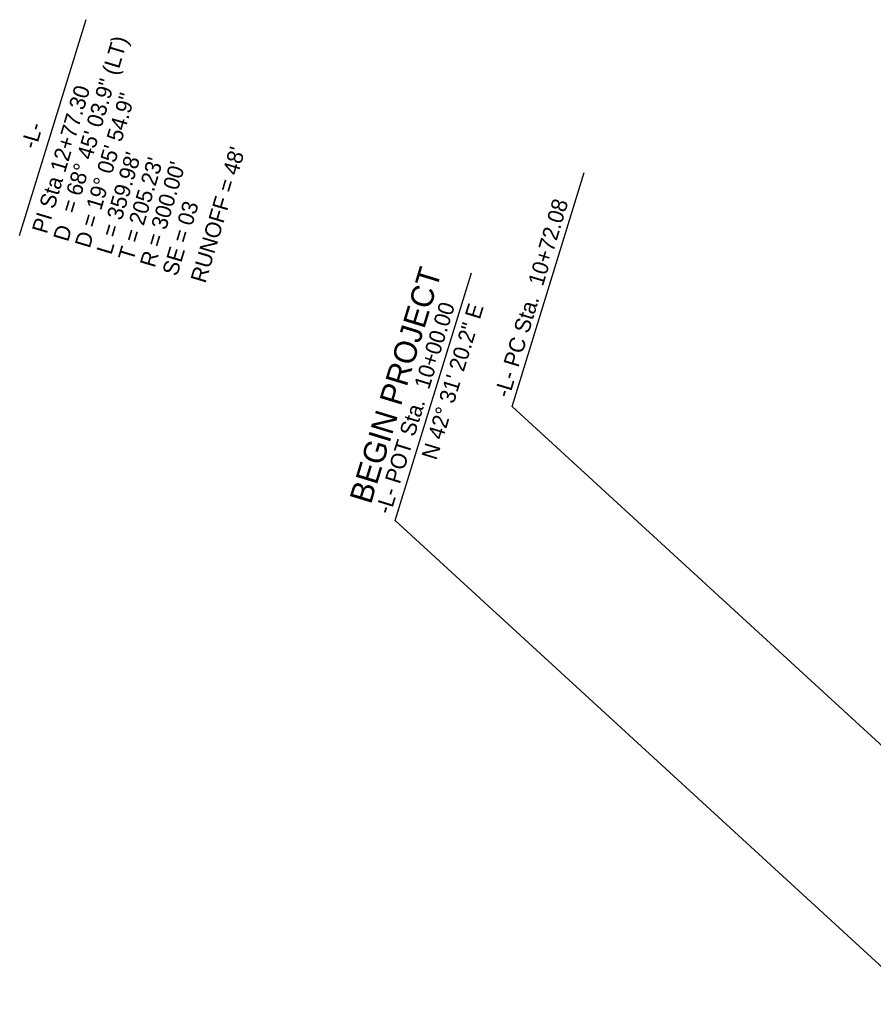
# Model space of a CAD drawing. Extents: x 1348352 to 1349119, y 1028998 to 1029749.
# Drawn here: x 1348351.6 to 1348729, y 1029075.3 to 1029508.1 of the extents above; entities that cross this region are included whole.
import ezdxf

# ---------------------------------------------------------------- set-up
doc = ezdxf.new("R2010")
doc.units = 0
for name, color, linetype in [('Prop DSN Text', 7, 'Continuous'), ('Prop Horizontal Alignment Curve and Spiral Data', 7, 'Continuous'), ('Prop Horizontal Alignment Direction Label', 7, 'Continuous'), ('Prop Horizontal Alignment Station Label', 7, 'Continuous')]:
    doc.layers.add(name, color=color, linetype=linetype)

msp = doc.modelspace()

# ---------------------------------------------------------------- linework, layer by layer
at = {"layer": 'Prop Horizontal Alignment Station Label'}
for p, q in [((1348351.59, 1029412.81), (1348380.95, 1029508.13)), ((1348569.31, 1029337.19), (1348601.13, 1029440.53)), ((1348517.58, 1029286.83), (1348551.28, 1029396.27)), ((1348796.98, 1029128.41), (1348569.31, 1029337.19)), ((1348748.26, 1029075.29), (1348517.58, 1029286.83))]:
    msp.add_line(p, q, dxfattribs=at)

# ---------------------------------------------------------------- texts
at = {"layer": 'Prop DSN Text'}
msp.add_text('BEGIN PROJECT', height=10, rotation=73.074, dxfattribs=at).set_placement((1348506.86, 1029293.68))
at = {"layer": 'Prop Horizontal Alignment Curve and Spiral Data'}
for s, p in [('= 68%%d 45\' 03.9" (LT)', (1348376.39, 1029422.05)), ('PI Sta 12+77.30', (1348363.6, 1029413.16)), ('D = 19%%d 05\' 54.9"', (1348382.57, 1029406.79)), ("RUNOFF = 48'", (1348433.72, 1029391.32)), ("L = 359.98'", (1348392.15, 1029403.92)), ("T = 205.23'", (1348401.73, 1029401.06)), ("R = 300.00'", (1348411.31, 1029398.19)), ('SE = 03', (1348421.23, 1029394.46)), ('D', (1348372.99, 1029409.65))]:
    msp.add_text(s, height=7, rotation=73.3547, dxfattribs=at).set_placement(p)
at = {"layer": 'Prop Horizontal Alignment Direction Label'}
msp.add_text('N 42%%d 31\' 20.2" E', height=7, rotation=72.8834, dxfattribs=at).set_placement((1348535.82, 1029313.16))
at = {"layer": 'Prop Horizontal Alignment Station Label'}
for s, rotation, p in [('-L-', 73.5959, (1348358.78, 1029450.53)), ('-L- PC Sta.  10+72.08', 73.2015, (1348567.99, 1029340.69)), ('-L- POT Sta.  10+00.00', 72.8281, (1348515.49, 1029289.23))]:
    msp.add_text(s, height=7, rotation=rotation, dxfattribs=at).set_placement(p)

doc.saveas('drawing.dxf')
